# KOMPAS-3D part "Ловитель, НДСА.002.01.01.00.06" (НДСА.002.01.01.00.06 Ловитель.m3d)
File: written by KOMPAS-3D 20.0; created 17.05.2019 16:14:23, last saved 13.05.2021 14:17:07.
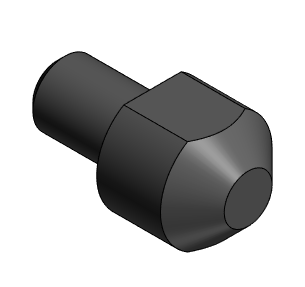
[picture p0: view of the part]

Document properties: Автор: Пользователь Windows; Полное имя файла: C:\Users\korychko\Desktop\PLM\НДСА.002.01.01.00.06 Ловитель.m3d

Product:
- Part/product: Ловитель  | designation НДСА.002.01.01.00.06
    Материал: Сталь 12Х18Н10Т ГОСТ 5632-2014 (density 7900 kg/m3)
    Масса: 0.0162591
    additional columns: <item xmlns="http://appius.ru/pdm" xmlns:xs="http://www.w3.org/2001/XMLSchema" x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; <item xmlns="http://appius.ru/pdm" xmlns:xs="http://www.w3.org/2001/XMLSchema" x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; <item xmlns="http://appius.ru/pdm" xmlns:xs="http://www.w3.org/2001/XMLSchema" x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; <item xmlns="http://appius.ru/pdm" xmlns:xs="http://www.w3.org/2001/XMLSchema" x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; <item xmlns="http://appius.ru/pdm" xmlns:xs="http://www.w3.org/2001/XMLSchema" x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; <item xmlns="http://appius.ru/pdm" xmlns:xs="http://www.w3.org/2001/XMLSchema" x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; <item xmlns="http://appius.ru/pdm" xmlns:xs="http://www.w3.org/2001/XMLSchema" x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; <item xmlns="http://appius.ru/pdm" xmlns:xs="http://www.w3.org/2001/XMLSchema" x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
    source file: НДСА.002.01.01.00.06 Ловитель.cdw

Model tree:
1. Эскиз:1
2. Элемент выдавливания:1
     Расстояние 1 = 12
3. Эскиз:2  (with: Элемент выдавливания:1)
4. Элемент выдавливания:2
     Расстояние 1 = 12
5. Условное изображение резьбы:1  (with: Элемент выдавливания:2)  (labels: cil0_24705-2004 coarse; M8)
     Длина резьбы = 14; Шаг резьбы = 1.25; Номинальный диаметр резьбы = 8
6. Подгонка:1  (with: Элемент выдавливания:2)
7. Фаска:1  (with: Элемент выдавливания:2)
     Угол = 45; Длина 1 = 1; Длина 2 = 1
8. Фаска:2  (with: Элемент выдавливания:1)
     Угол = 45; Длина 1 = 4; Длина 2 = 4
9. Ось конической поверхности:2  (with: Элемент выдавливания:2)
10. Смещенная плоскость:2  (with: Элемент выдавливания:1)
11. ЛСК:2  (with: Плоскость XY, Плоскость ZX, Плоскость ZY, Ось X, Ось Y, Ось Z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)
     Ось X. X = 1; Ось Y. Y = 1; Ось Z. Z = 1; Точка начала. Х = 12
12. Эскиз:6
13. Эскиз:7
14. Элемент вращения:3
     Угол 1 = 360
15. Элемент вращения:4
     Угол 1 = 360
16. Проточка наружная M8x0,5 Н ГОСТ 10549-80
17. Эскиз:5  (with: Элемент выдавливания:1)
18. Элемент выдавливания:3  (labels: Сталь 12Х18Н10Т ГОСТ 5632-2014)
     Расстояние 2 = 10

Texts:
  KTE.LIST=Du7ArA6Td4KLoATnVjMlQc; KTE.LIST=gVt5qV3zafSUUmu7llP6.d
  Edge1
  Edge2
  НДСА.002.01.01.00.06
